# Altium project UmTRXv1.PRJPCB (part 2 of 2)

## Sheet EEpromConfig.SchDoc: BaseBand Front-End
size A3; Revision: 1; SheetNumber: 7
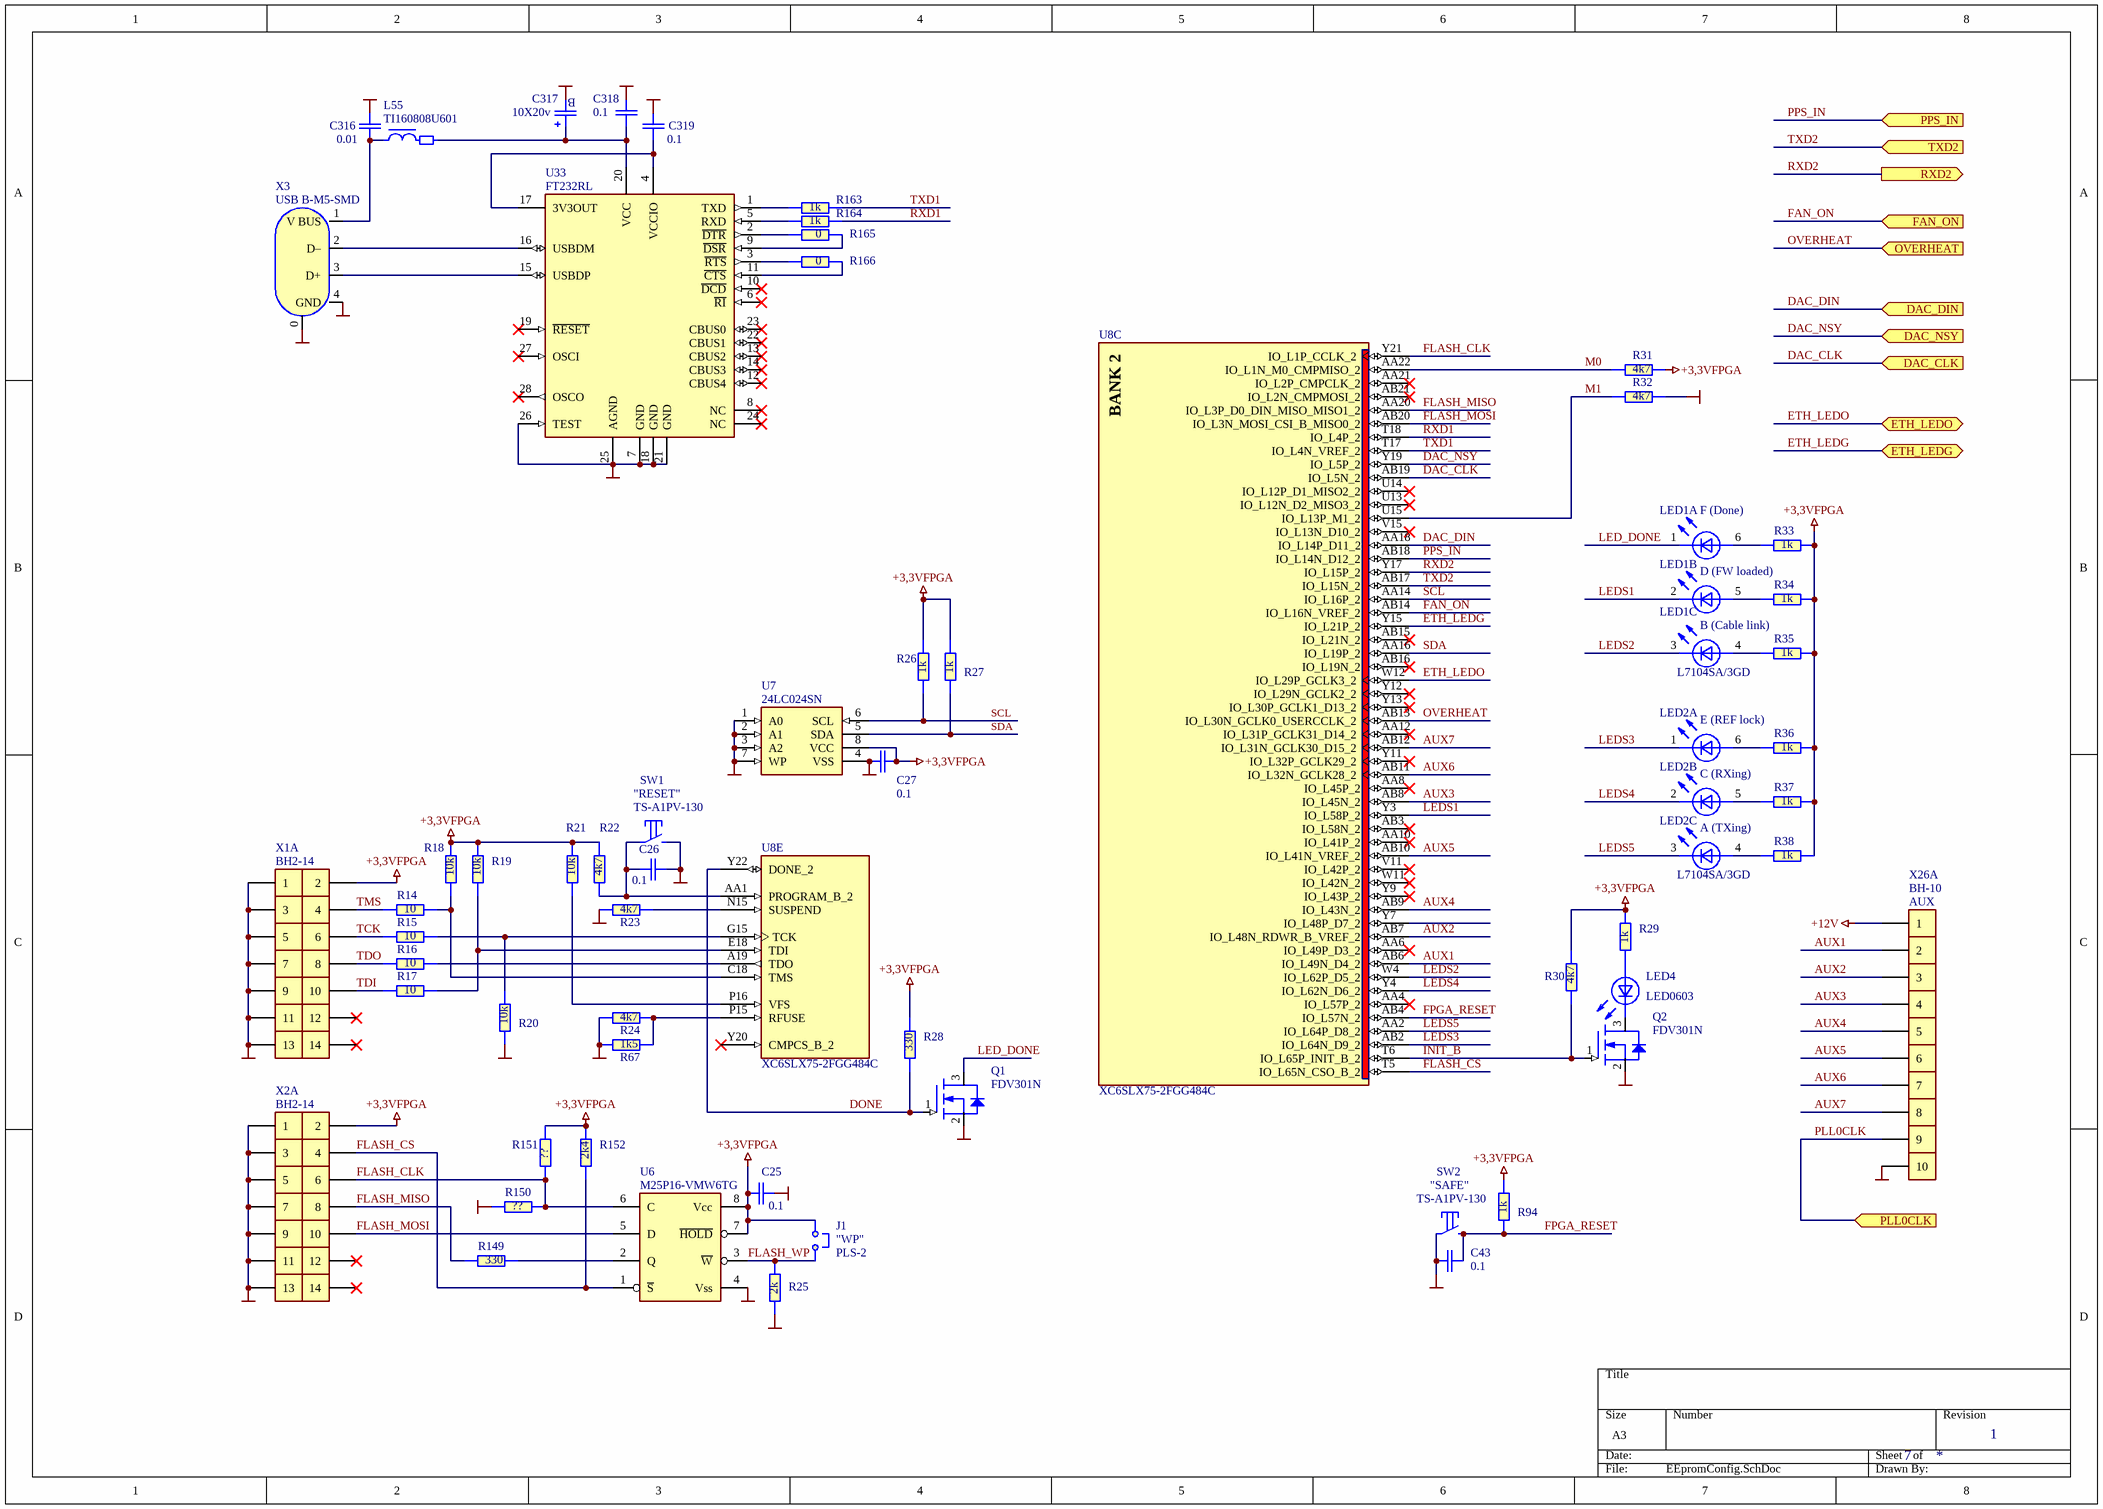
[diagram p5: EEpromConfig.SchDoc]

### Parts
C25  0.1  [C0402-Phillips]
C26  0.1  [C0402-Phillips]
C27  0.1  [C0402-Phillips]
C43  0.1  [C0402-Phillips]
C316  0.01  [C0603-PHILLIPS]
C317  10X20v  [CB3528]
C318  0.1  [C0603-PHILLIPS]
C319  0.1  [C0603-PHILLIPS]
J1  PLS-2  misc: "WP"  [PLT-2]
L55  TI160808U601  [Ti160808-Phillips]
LED1  L7104SA/3GD  [L-7104SA/3]  (value not drawn)  (parts A,B,C of 3)
LED2  L7104SA/3GD  [L-7104SA/3]  (value not drawn)  (parts A,B,C of 3)
LED4  LED0603  [LED-0603y]
Q1  FDV301N  [SOT23-Philips]
Q2  FDV301N  [SOT23-Philips]
R14  10  [R0603-PHILLIPS]
R15  10  [R0603-PHILLIPS]
R16  10  [R0603-PHILLIPS]
R17  10  [R0603-PHILLIPS]
R18  10k  [R0603-PHILLIPS]
R19  10k  [R0603-PHILLIPS]
R20  10k  [R0603-PHILLIPS]
R21  10k  [R0603-PHILLIPS]
R22  4k7  [R0603-PHILLIPS]
R23  4k7  [R0603-PHILLIPS]
R24  4k7  [R0603-PHILLIPS]
R25  2k  [R0603-PHILLIPS]
R26  1k  [R0603-PHILLIPS]
R27  1k  [R0603-PHILLIPS]
R28  330  [R0603-PHILLIPS]
R29  1k  [R0603-PHILLIPS]
R30  4k7  [R0603-PHILLIPS]
R31  4k7  [R0603-PHILLIPS]
R32  4k7  [R0603-PHILLIPS]
R33  1k  [R0603-PHILLIPS]
R34  1k  [R0603-PHILLIPS]
R35  1k  [R0603-PHILLIPS]
R36  1k  [R0603-PHILLIPS]
R37  1k  [R0603-PHILLIPS]
R38  1k  [R0603-PHILLIPS]
R67  1k5  [R0603-PHILLIPS]
R94  1k  [R0603-PHILLIPS]
R149  330  [R0603-PHILLIPS]
R150  ??  [R0603-PHILLIPS]
R151  ??  [R0603-PHILLIPS]
R152  2k4  [R0603-PHILLIPS]
R163  1k  [R0603-PHILLIPS]
R164  1k  [R0603-PHILLIPS]
R165  0  [R0603-PHILLIPS]
R166  0  [R0603-PHILLIPS]
SW1  TS-A1PV-130  misc: "RESET"  [KNOPKA]
SW2  TS-A1PV-130  misc: "SAFE"  [KNOPKA]
U6  M25P16-VMW6TG  [SOIC8]
U7  24LC024SN  [SOIC8]
U8  XC6SLX75-2FGG484C  [FBGA484]  (parts C,E of 8)
U33  FT232RL  [SSOP-28(5.3X10/0.65)]
X1  BH2-14  [BH2-14]  (value not drawn)  (parts A,B,C,D,E,F,G,H,I,J,K,L,M,N of 14)
X2  BH2-14  [BH2-14]  (value not drawn)  (parts A,B,C,D,E,F,G,H,I,J,K,L,M,N of 14)
X3  USB B-M5-SMD  [USB/SM0.8-6H5]
X26  BH-10  value AUX  [BH-10]  (parts A,B,C,D,E,F,G,H,I,J of 10)

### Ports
DAC_CLK (in), DAC_DIN (in), DAC_NSY (in), ETH_LEDG, ETH_LEDO, FAN_ON (in), OVERHEAT (in), PLL0CLK (in), PPS_IN (in), RXD2 (out), TXD2 (in)

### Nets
+3,3VFPGA: C25.1 C27.2 J1.1 R18.1 R19.1 R21.1 R22.1 R26.1 R27.1 R28.1 R29.1 R30.1 R31.2 R33.1 R34.1 R35.1 R36.1 R37.1 R38.1 R94.1 R151.1 R152.1 U6.7(~{HOLD}) U6.8(Vcc) U7.8(VCC) X1.2 X2.2
+12V: X26.1
GND: C25.2 C26.2 C27.1 C43.1 C316.1 C317.2(-) C318.1 C319.1 Q1.2(S) Q2.2(S) R20.2 R23.1 R24.1 R25.2 R32.2 R67.1 R150.1 SW1.2 SW2.1 U6.4(Vss) U7.1(A0) U7.2(A1) U7.3(A2) U7.4(VSS) U7.7(WP) U33.7(GND) U33.18(GND) U33.21(GND) U33.25(AGND) U33.26(TEST) X1.1 X1.3 X1.5 X1.7 X1.9 X1.11 X1.13 X2.1 X2.3 X2.5 X2.7 X2.9 X2.11 X2.13 X3.0(GND) X3.4(GND) X26.10
AUX1: U8.AB6(IO_L49N_D4_2) X26.2
AUX2: U8.AB7(IO_L48N_RDWR_B_VREF_2) X26.3
AUX3: U8.AB8(IO_L45N_2) X26.4
AUX4: U8.AB9(IO_L43N_2) X26.5
AUX5: U8.AB10(IO_L41N_VREF_2) X26.6
AUX6: U8.AB11(IO_L32N_GCLK28_2) X26.7
AUX7: U8.AB12(IO_L31N_GCLK30_D15_2) X26.8
DAC_CLK: U8.AB19(IO_L5N_2) ; port DAC_CLK
DAC_DIN: U8.AA18(IO_L14P_D11_2) ; port DAC_DIN
DAC_NSY: U8.Y19(IO_L5P_2) ; port DAC_NSY
DONE: Q1.1(G) R28.2 U8.Y22(DONE_2)
ETH_LEDG: U8.Y15(IO_L21P_2) ; port ETH_LEDG
ETH_LEDO: U8.W12(IO_L29P_GCLK3_2) ; port ETH_LEDO
FAN_ON: U8.AB14(IO_L16N_VREF_2) ; port FAN_ON
FLASH_CLK: R150.2 R151.2 U6.6(C) U8.Y21(IO_L1P_CCLK_2) X2.6
FLASH_CS: R152.2 U6.1(~{S}) U8.T5(IO_L65N_CSO_B_2) X2.4
FLASH_MISO: R149.1 U8.AA20(IO_L3P_D0_DIN_MISO_MISO1_2) X2.8
FLASH_MOSI: U6.5(D) U8.AB20(IO_L3N_MOSI_CSI_B_MISO0_2) X2.10
FLASH_WP: J1.2 R25.1 U6.3(~{W})
FPGA_RESET: C43.2 R94.2 SW2.2 U8.AB4(IO_L57N_2)
INIT_B: Q2.1(G) R30.2 U8.T6(IO_L65P_INIT_B_2)
LED_DONE: LED1.1(K1) Q1.3(D)
LEDS1: LED1.2(K2) U8.Y3(IO_L58P_2)
LEDS2: LED1.3(K3) U8.W4(IO_L62P_D5_2)
LEDS3: LED2.1(K1) U8.AB2(IO_L64N_D9_2)
LEDS4: LED2.2(K2) U8.Y4(IO_L62N_D6_2)
LEDS5: LED2.3(K3) U8.AA2(IO_L64P_D8_2)
M0: R31.1 U8.AA22(IO_L1N_M0_CMPMISO_2)
M1: R32.1 U8.U15(IO_L13P_M1_2)
OVERHEAT: U8.AB13(IO_L30N_GCLK0_USERCCLK_2) ; port OVERHEAT
PLL0CLK: X26.9 ; port PLL0CLK
PPS_IN: U8.AB18(IO_L14N_D12_2) ; port PPS_IN
RXD1: R164.1 U8.T18(IO_L4P_2)
RXD2: U8.Y17(IO_L15P_2) ; port RXD2
SCL: R26.2 U7.6(SCL) U8.AA14(IO_L16P_2)
SDA: R27.2 U7.5(SDA) U8.AA16(IO_L19P_2)
TCK: R15.1 X1.6
TDI: R17.1 X1.10
TDO: R16.1 X1.8
TMS: R14.1 X1.4
TXD1: R163.1 U8.T17(IO_L4N_VREF_2)
TXD2: U8.AB17(IO_L15N_2) ; port TXD2
NetC26_1: C26.1 R22.2 SW1.1 U8.AA1(PROGRAM_B_2)
NetC316_2: C316.2 L55.1 X3.1(V_BUS)
NetC317_1: C317.1(+) C318.2 L55.2 U33.20(VCC)
NetC319_2: C319.2 U33.4(VCCIO) U33.17(3V3OUT)
NetLED1_4: LED1.4(A3) R35.2
NetLED1_5: LED1.5(A2) R34.2
NetLED1_6: LED1.6(A1) R33.2
NetLED2_4: LED2.4(A3) R38.2
NetLED2_5: LED2.5(A2) R37.2
NetLED2_6: LED2.6(A1) R36.2
NetLED4_1: LED4.1(K) Q2.3(D)
NetLED4_2: LED4.2(A) R29.2
NetR14_2: R14.2 R18.2 U8.C18(TMS)
NetR15_2: R15.2 R20.1 U8.G15(TCK)
NetR16_2: R16.2 U8.A19(TDO)
NetR17_2: R17.2 R19.2 U8.E18(TDI)
NetR21_2: R21.2 U8.P16(VFS)
NetR23_2: R23.2 U8.N15(SUSPEND)
NetR24_2: R24.2 R67.2 U8.P15(RFUSE)
NetR149_2: R149.2 U6.2(Q)
NetR163_2: R163.2 U33.1(TXD)
NetR164_2: R164.2 U33.5(RXD)
NetR165_1: R165.1 U33.2(~{DTR})
NetR165_2: R165.2 U33.9(~{DSR})
NetR166_1: R166.1 U33.3(~{RTS})
NetR166_2: R166.2 U33.11(~{CTS})
NetU33_15: U33.15(USBDP) X3.3(D+)
NetU33_16: U33.16(USBDM) X3.2(D–)

Not connected (* = marked no-connect by the designer): U8 AA4(IO_L57P_2)* AA6(IO_L49P_D3_2)* AA8(IO_L45P_2)* AA10(IO_L41P_2)* AA12(IO_L31P_GCLK31_D14_2)* AA21(IO_L2P_CMPCLK_2)* AB3(IO_L58N_2)* AB15(IO_L21N_2)* AB16(IO_L19N_2)* AB21(IO_L2N_CMPMOSI_2)* U13(IO_L12N_D2_MISO3_2)* U14(IO_L12P_D1_MISO2_2)* V11(IO_L42P_2)* V15(IO_L13N_D10_2)* W11(IO_L42N_2)* Y7(IO_L48P_D7_2) Y9(IO_L43P_2)* Y11(IO_L32P_GCLK29_2)* Y12(IO_L29N_GCLK2_2)* Y13(IO_L30P_GCLK1_D13_2)* Y20(CMPCS_B_2)*; U33 6(~{RI})* 8(NC)* 10(~{DCD})* 12(CBUS4)* 13(CBUS2)* 14(CBUS3)* 19(~{RESET})* 22(CBUS1)* 23(CBUS0)* 24(NC)* 27(OSCI)* 28(OSCO)*; X1 12* 14*; X2 12* 14*

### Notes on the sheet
- F (Done)
- D (FW loaded)
- B (Cable link)
- E (REF lock)
- (near LED2) C (RXing)
- (near LED2) A (TXing)

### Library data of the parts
C25-C27 C43 = C0402: Конденсатор; Manufacturer: MURATA; Tolerance: 20%; Name: SMD0402; U/P/TKE: Y5V
C316 C318 C319 = C0603: Конденсатор; Manufacturer: MURATA; Tolerance: 20%; Name: SMD0603; U/P/TKE: Y5V
C317 = CB3528: Конденсатор; Manufacturer: SPRAGUE; Name: Case B; U/P/TKE: 20V
J1 = JUMP-2: Перемычка; Manufacturer: BM
L55 = TI160808: Дроссель ЭМС; Manufacturer: MURATA
LED1 LED2 = L7104SA/3: Светодиод; Manufacturer: KINGBRIGTH; PDF: d:\Proj\Components\Kingbright\L-7104SA-3GD(Ver.4).pdf
LED4 = LED0603: Светодиод
Q1 Q2 = FDV301N: Транзистор; Manufacturer: Fairchild; PDF: D:\Proj\Components\FairChild\FDV301N.pdf
R14-R38 R67 R94 R149-R152 R163-R166 = R0603: Резистор; Manufacturer: YAGEO; Tolerance: 5%; Name: SMD0603; U/P/TKE: 0.1W
SW1 SW2 = KNOPKA: Кнопка; Manufacturer: Alps
U6 = M25P40-VMN6T: Микросхема; Manufacturer: ST; Swap: No; PDF: d:\Proj\Components\ST\M25P40.pdf
U7 = AT24CXX: Микросхема; Manufacturer: Microchip; Swap: No; PDF: d:\Proj\components\Atmel\AT24C02A_04A_08A_16A.pdf; PDF2: d:\Proj\Components\Atmel\AT24C04B_08B.pdf
U8 = XC6SLX75-2FGG484C: Spartan-6 LX 1.2V FPGA, 270 User I/Os, 484-Ball Fine-Pitch BGA (1.0mm Pitch), Speed Grade 2, Commercial Grade, Pb-Free; Manufacturer: Xilinx
U33 = FT232RL: Микросхема; Manufacturer: FTDI; Misc: USB UART Asynchronous Serial Data Transfer Chip,
X1 X2 = BH2-14: Разъем; Manufacturer: BM
X3 = USB M-1J: Разъём
X26 = BH-10: Разъем; Manufacturer: BM

## Sheet Clocking.SchDoc: BaseBand Front-End
size A3; Revision: 1; SheetNumber: 5
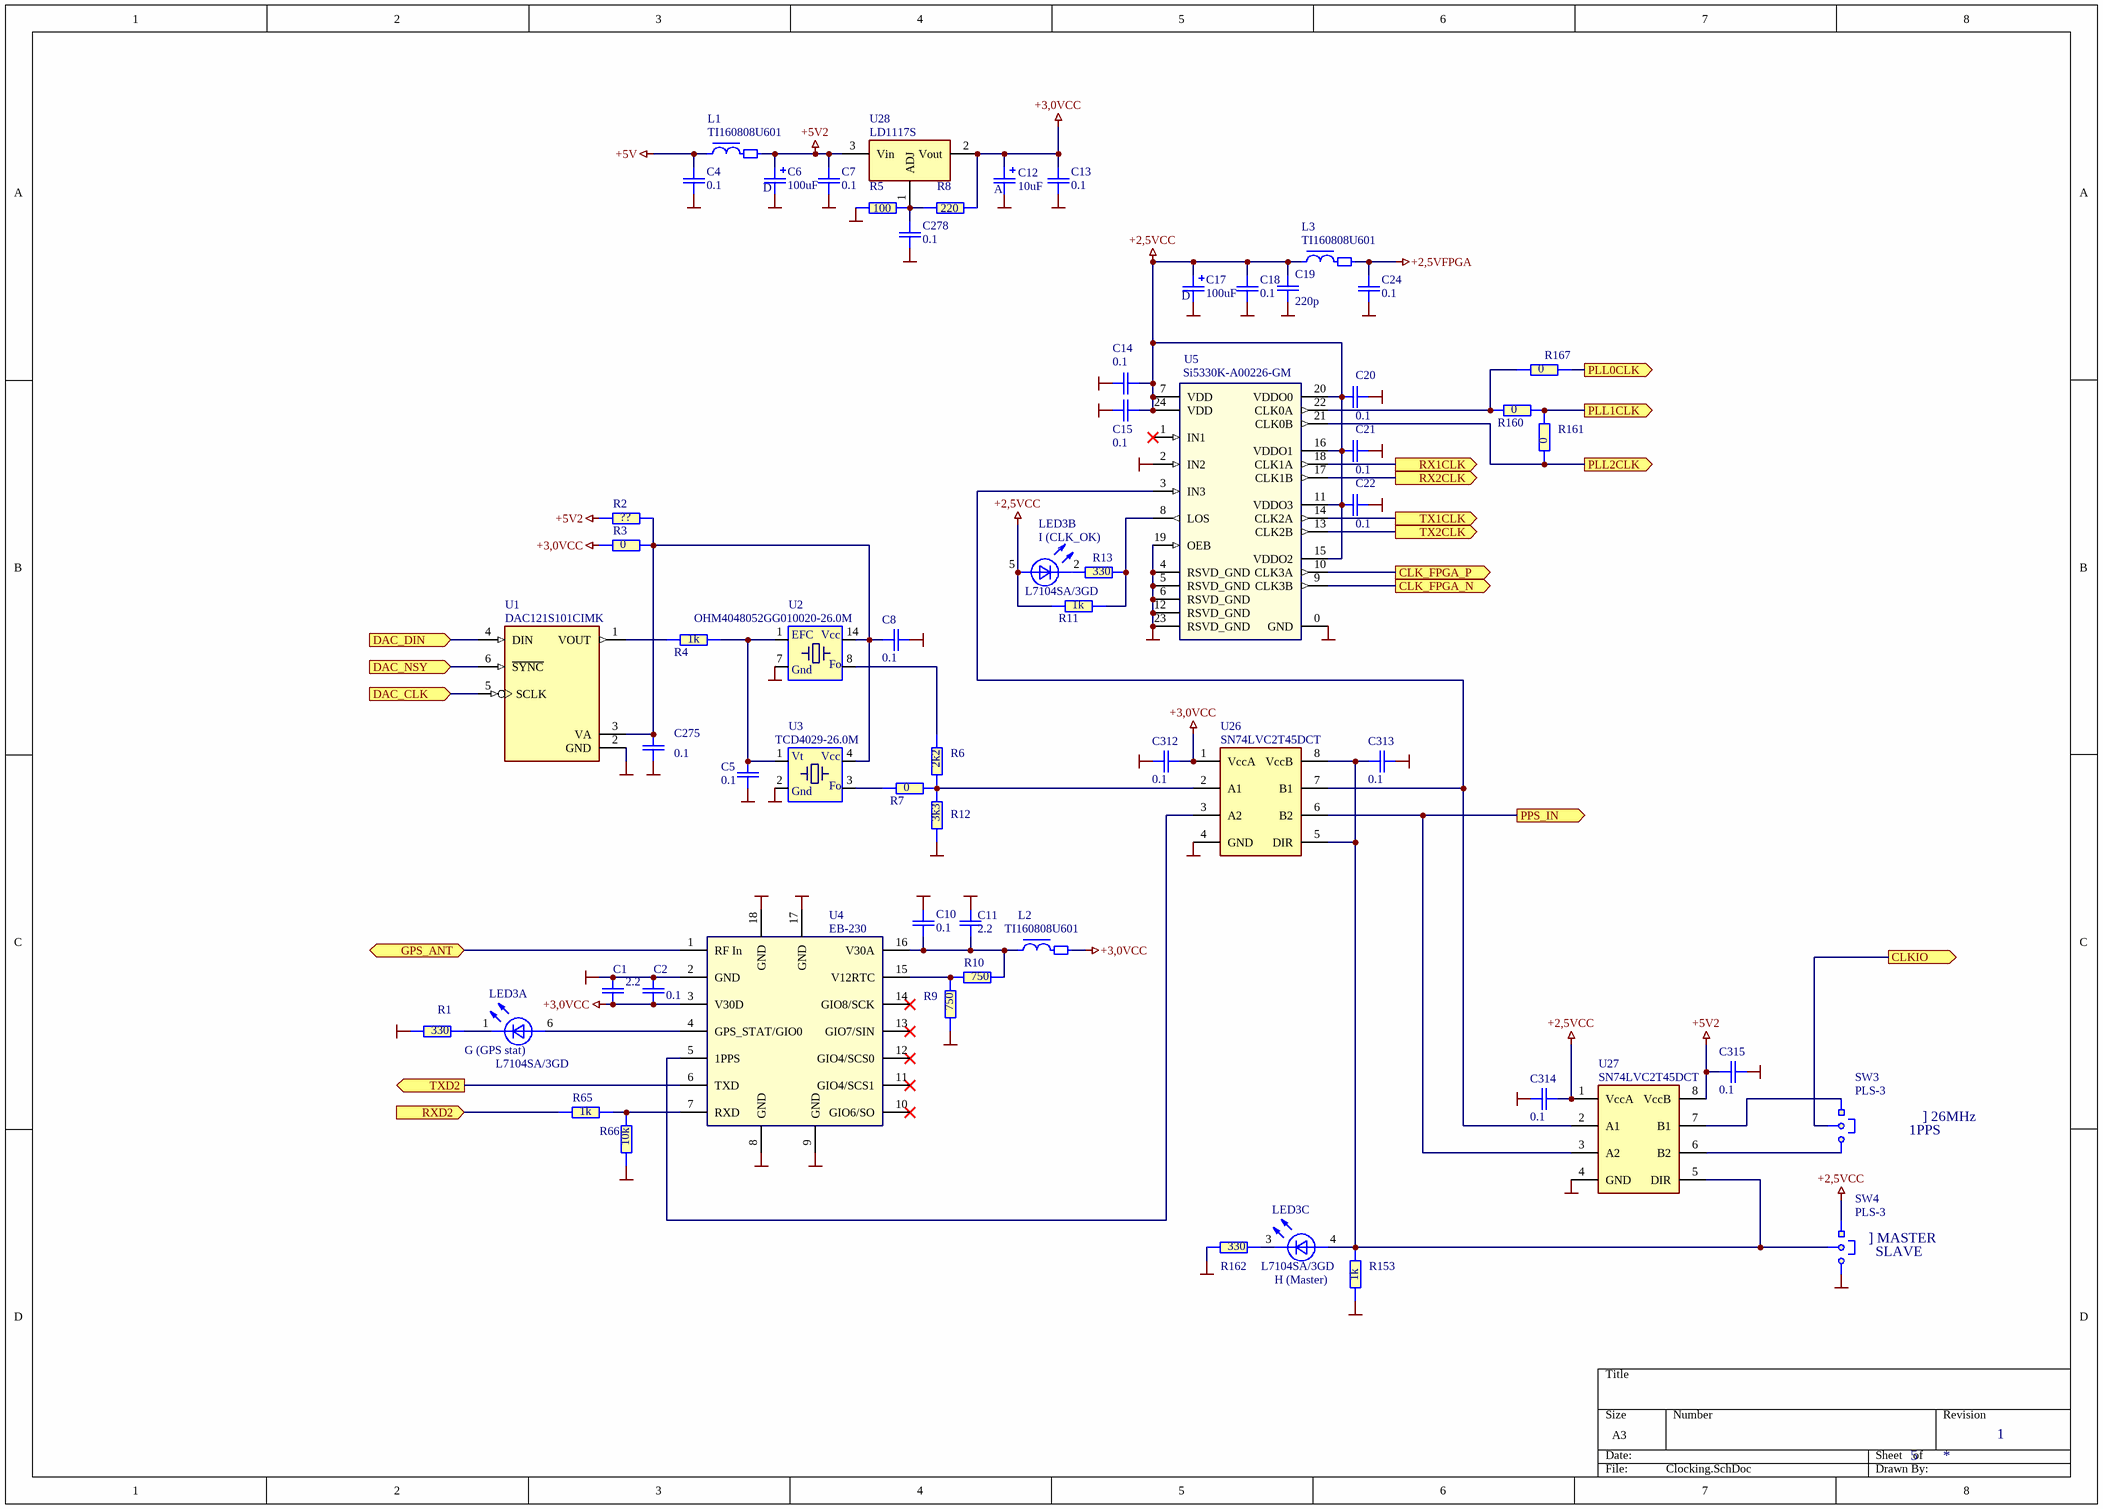
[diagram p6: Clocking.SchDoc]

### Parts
C1  2.2  [C0402-Phillips]
C2  0.1  [C0402-Phillips]
C4  0.1  [C0402-Phillips]
C5  0.1  [C0402-Phillips]
C6  100uF  [cd7343]
C7  0.1  [C0402-Phillips]
C8  0.1  [C0402-Phillips]
C10  0.1  [C0402-Phillips]
C11  2.2  [C0402-Phillips]
C12  10uF  [CA3216]
C13  0.1  [C0402-Phillips]
C14  0.1  [C0402-Phillips]
C15  0.1  [C0402-Phillips]
C17  100uF  [cd7343]
C18  0.1  [C0402-Phillips]
C19  220p  [C0603-PHILLIPS]
C20  0.1  [C0402-Phillips]
C21  0.1  [C0402-Phillips]
C22  0.1  [C0402-Phillips]
C24  0.1  [C0402-Phillips]
C275  0.1  [C0402-Phillips]
C278  0.1  [C0402-Phillips]
C312  0.1  [C0402-Phillips]
C313  0.1  [C0402-Phillips]
C314  0.1  [C0402-Phillips]
C315  0.1  [C0402-Phillips]
L1  TI160808U601  [Ti160808-Phillips]
L2  TI160808U601  [Ti160808-Phillips]
L3  TI160808U601  [Ti160808-Phillips]
LED3  L7104SA/3GD  [L-7104SA/3]  (parts A,B,C of 3)
R1  330  [R0603-PHILLIPS]
R2  ??  [R0603-PHILLIPS]
R3  0  [R0603-PHILLIPS]
R4  1k  [R0603-PHILLIPS]
R5  100  [R0603-PHILLIPS]
R6  2k2  [R0603-PHILLIPS]
R7  0  [R0603-PHILLIPS]
R8  220  [R0603-PHILLIPS]
R9  750  [R0603-PHILLIPS]
R10  750  [R0603-PHILLIPS]
R11  1k  [R0603-PHILLIPS]
R12  3k3  [R0603-PHILLIPS]
R13  330  [R0603-PHILLIPS]
R65  1k  [R0603-PHILLIPS]
R66  10k  [R0603-PHILLIPS]
R153  1k  [R0603-PHILLIPS]
R160  0  [R0603-PHILLIPS]
R161  0  [R0603-PHILLIPS]
R162  330  [R0603-PHILLIPS]
R167  0  [R0603-PHILLIPS]
SW3  PLS-3  [PLT-3]
SW4  PLS-3  [PLT-3]
U1  DAC121S101CIMK  [SOT-23-6]
U2  OHM4048052GG010020-26.0M  [DIL14-20x13,2]
U3  TCD4029-26.0M  [TCXO7X5]
U4  EB-230  [EB-230]
U5  Si5330K-A00226-GM  [QFN-24(4x4/0/5mm) with Pad]
U26  SN74LVC2T45DCT  [SO-8-MICRO]
U27  SN74LVC2T45DCT  [SO-8-MICRO]
U28  LD1117S  [SOT-223-1]

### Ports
CLK_FPGA_N (out), CLK_FPGA_P (out), CLKIO (out), DAC_CLK (in), DAC_DIN (in), DAC_NSY (in), GPS_ANT, PLL0CLK (out), PLL1CLK (out), PLL2CLK (out), PPS_IN (out), RX1CLK (out), RX2CLK (out), RXD2 (in), TX1CLK (out), TX2CLK (out), TXD2 (out)

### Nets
+2,5VCC: C14.2 C15.2 C17.1(+) C18.1 C19.1 C20.1 C21.1 C22.1 C314.1 L3.1 LED3.5(A2) R11.1 SW4.1 U5.7(VDD) U5.11(VDDO3) U5.15(VDDO2) U5.16(VDDO1) U5.20(VDDO0) U5.24(VDD) U27.1(VccA)
+2,5VFPGA: C24.1 L3.2
+3,0VCC: C1.1 C2.1 C12.1(+) C13.1 C312.1 L2.2 R3.1 R8.2 U4.3(V30D) U26.1(VccA) U28.2(Vout)
+5V: C4.1 L1.1
+5V2: C6.1(+) C7.1 C315.2 L1.2 R2.1 U27.8(VccB) U28.3(Vin)
GND: C1.2 C2.2 C4.2 C5.1 C6.2(-) C7.2 C8.2 C10.2 C11.2 C12.2(-) C13.2 C14.1 C15.1 C17.2(-) C18.2 C19.2 C20.2 C21.2 C22.2 C24.2 C275.1 C278.2 C312.2 C313.1 C314.2 C315.1 R1.1 R5.1 R9.1 R12.1 R66.1 R153.1 R162.1 SW4.3 U1.2(GND) U2.7(GND) U3.2(GND) U4.2(GND) U4.8(GND) U4.9(GND) U4.17(GND) U4.18(GND) U5.0(GND) U5.2(IN2) U5.4(RSVD_GND) U5.5(RSVD_GND) U5.6(RSVD_GND) U5.12(RSVD_GND) U5.19(OEB) U5.23(RSVD_GND) U26.4(GND) U27.4(GND)
CLK_FPGA_N: U5.9(CLK3B) ; port CLK_FPGA_N
CLK_FPGA_P: U5.10(CLK3A) ; port CLK_FPGA_P
CLKIO: SW3.2 ; port CLKIO
DAC_CLK: U1.5(SCLK) ; port DAC_CLK
DAC_DIN: U1.4(DIN) ; port DAC_DIN
DAC_NSY: U1.6(~{SYNC}) ; port DAC_NSY
GPS_ANT: U4.1(RF_In) ; port GPS_ANT
PLL0CLK: R167.2 ; port PLL0CLK
PLL1CLK: R160.2 R161.1 ; port PLL1CLK
PLL2CLK: R161.2 U5.21(CLK0B) ; port PLL2CLK
PPS_IN: U26.6(B2) U27.3(A2) ; port PPS_IN
RX1CLK: U5.18(CLK1A) ; port RX1CLK
RX2CLK: U5.17(CLK1B) ; port RX2CLK
RXD2: R65.1 ; port RXD2
TX1CLK: U5.14(CLK2A) ; port TX1CLK
TX2CLK: U5.13(CLK2B) ; port TX2CLK
TXD2: U4.6(TXD) ; port TXD2
NetC5_2: C5.2 R4.2 U2.1(EFC) U3.1(Vtune)
NetC8_1: C8.1 C275.2 R2.2 R3.2 U1.3(VA) U2.14(VCC) U3.4(VCC)
NetC10_1: C10.1 C11.1 L2.1 R10.2 U4.16(V30A)
NetC278_1: C278.1 R5.2 R8.1 U28.1(ADJ)
NetC313_2: C313.2 LED3.4(A3) R153.2 SW4.2 U26.5(DIR) U26.8(VccB) U27.5(DIR)
NetLED3_1: LED3.1(K1) R1.2
NetLED3_2: LED3.2(K2) R13.1
NetLED3_3: LED3.3(K3) R162.2
NetLED3_6: LED3.6(A1) U4.4(GPS_STAT/GIO0)
NetR4_1: R4.1 U1.1(VOUT)
NetR6_1: R6.1 U2.8(Fo)
NetR6_2: R6.2 R7.2 R12.2 U26.2(A1)
NetR7_1: R7.1 U3.3(Fo)
NetR9_2: R9.2 R10.1 U4.15(V12RTC)
NetR11_2: R11.2 R13.2 U5.8(LOS)
NetR65_2: R65.2 R66.2 U4.7(RXD)
NetR160_1: R160.1 R167.1 U5.22(CLK0A)
NetSW3_1: SW3.1 U27.7(B1)
NetSW3_3: SW3.3 U27.6(B2)
NetU4_5: U4.5(1PPS) U26.3(A2)
NetU5_3: U5.3(IN3) U26.7(B1) U27.2(A1)

Not connected (* = marked no-connect by the designer): U4 10(GIO6/SO)* 11(GIO4/SCS1)* 12(GIO4/SCS0)* 13(GIO7/SIN)* 14(GIO8/SCK)*; U5 1(IN1)*

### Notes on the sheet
- I (CLK_OK)
- G (GPS stat)
- (near SW3) ] 26MHz
- (near SW3) 1PPS
- (near SW4) ] MASTER
- (near SW4) SLAVE
- H (Master)

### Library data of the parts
C1 C2 C4 C5 C7 C8 C10 C11 C13-C15 C18 C20-C22 C24 C275 C278 C312-C315 = C0402: as C25-C27 on sheet EEpromConfig
C6 C17 = CD7343: Конденсатор; Manufacturer: SPRAGUE; Name: CASE-G; U/P/TKE: 16V
C12 = CA3216: Конденсатор; Manufacturer: SPRAGUE; Name: Case A; U/P/TKE: 10V
C19 = C0603: Конденсатор; Manufacturer: MURATA; Tolerance: 20%; Name: SMD0603; U/P/TKE: NP0
L1-L3 = TI160808: Дроссель ЭМС; Manufacturer: MURATA
LED3 = L7104SA/3: as LED1 on sheet EEpromConfig
R1-R13 R65 R66 R153 R160-R162 R167 = R0603: as R14-R38 on sheet EEpromConfig
SW3 SW4 = JUMP-3: Перемычка; Manufacturer: BM
U1 = DAC121S101CIMK: Микросхема; Manufacturer: National Semiconductor; Misc: 12-Bit Micro Power Digital-to-Analog Converter with Rail-to-Rail Output
U2 = OCVCXO: Manufacturer: Pletronics; Misc: TCXO
U3 = TCVCXO_5X3: TCVCXO; Manufacturer: Jauch; Misc: TCXO
U4 = EB-230: Модуль; Manufacturer: Transistem; PDF: d:\Proj\Components\OnSemiconductors\SMFxxC.pdf; Misc: GPS engine board
U5 = SI5330: Микросхема; Manufacturer: Silicon Laboratoryes; Misc: CLOCK BUFFER/LEVEL TRANSLATOR; Swap: No
U26 U27 = 74LVC2T45DCT: Микросхема; Manufacturer: TI; Swap: No
U28 = LD1117ADJ: Микросхема; Manufacturer: STMicro; Swap: No

## Sheet LMS.SchDoc
size A3; Revision: 1; SheetNumber: 3
Used 2 times, as channels LMS-a, LMS-b. Parts and nets are listed once, with the designators drawn on the sheet.
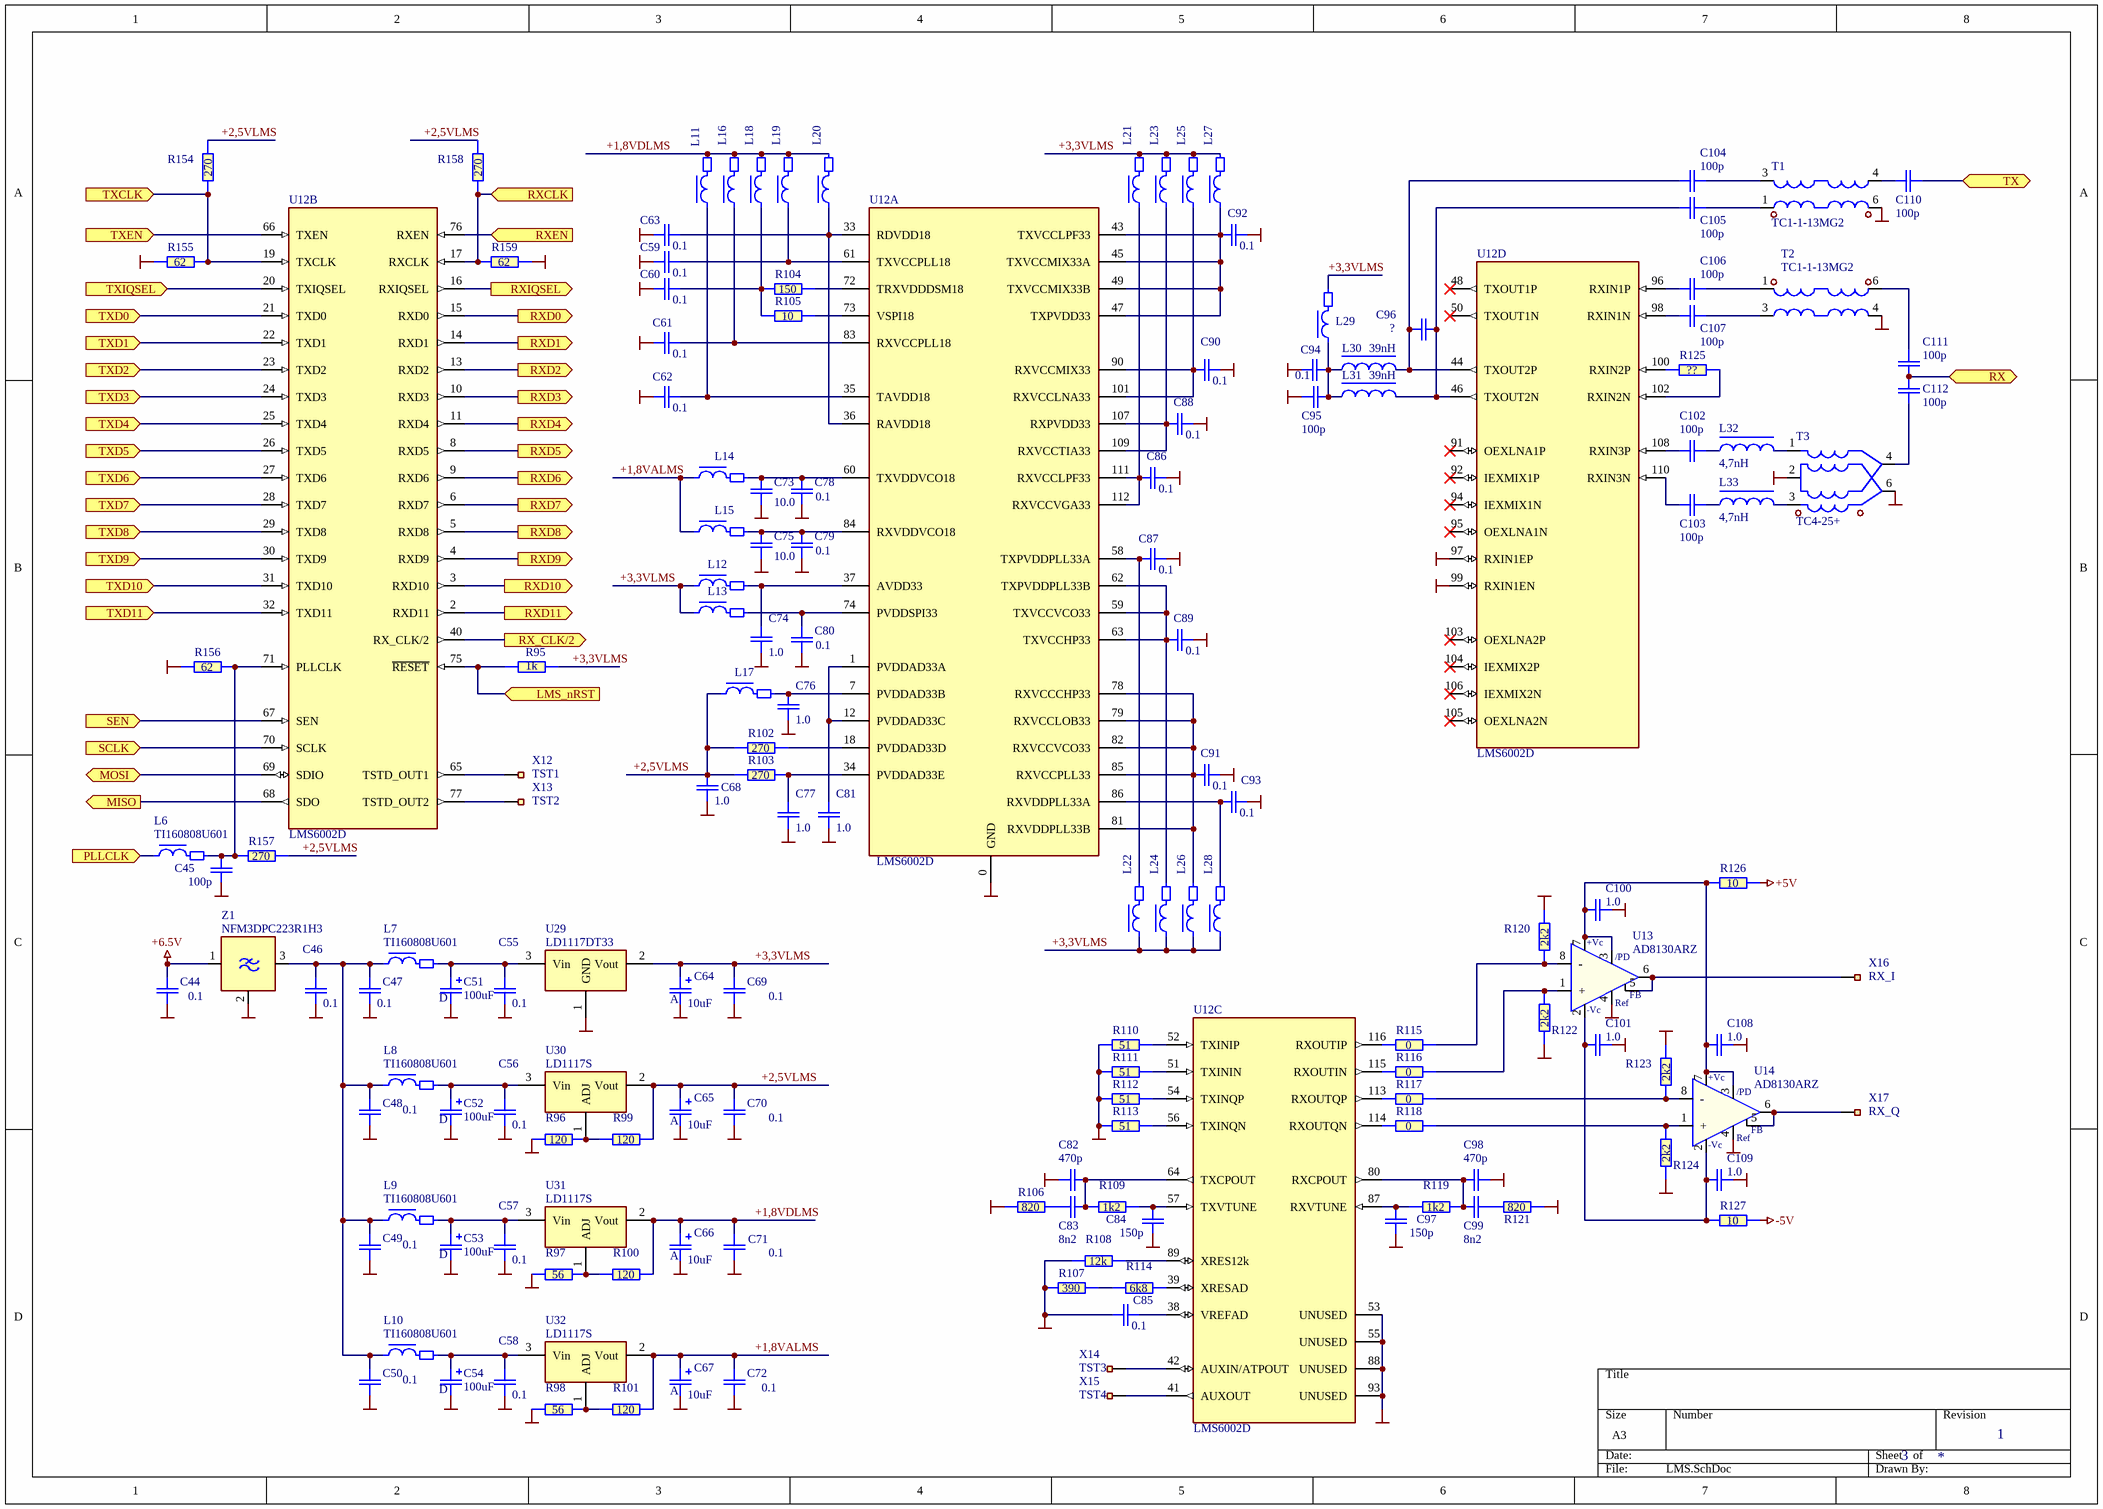
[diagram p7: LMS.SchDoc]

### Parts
C44  0.1  [C0402-Phillips]
C45  100p  [C0603-PHILLIPS]
C46  0.1  [C0402-Phillips]
C47  0.1  [C0402-Phillips]
C48  0.1  [C0402-Phillips]
C49  0.1  [C0402-Phillips]
C50  0.1  [C0402-Phillips]
C51  100uF  [cd7343]
C52  100uF  [cd7343]
C53  100uF  [cd7343]
C54  100uF  [cd7343]
C55  0.1  [C0402-Phillips]
C56  0.1  [C0402-Phillips]
C57  0.1  [C0402-Phillips]
C58  0.1  [C0402-Phillips]
C59  0.1  [C0402-Phillips]
C60  0.1  [C0402-Phillips]
C61  0.1  [C0402-Phillips]
C62  0.1  [C0402-Phillips]
C63  0.1  [C0402-Phillips]
C64  10uF  [CA3216]
C65  10uF  [CA3216]
C66  10uF  [CA3216]
C67  10uF  [CA3216]
C68  1.0  [C0603-PHILLIPS]
C69  0.1  [C0402-Phillips]
C70  0.1  [C0402-Phillips]
C71  0.1  [C0402-Phillips]
C72  0.1  [C0402-Phillips]
C73  10.0  [C0603-Phillips]
C74  1.0  [C0603-PHILLIPS]
C75  10.0  [C0603-Phillips]
C76  1.0  [C0603-PHILLIPS]
C77  1.0  [C0603-PHILLIPS]
C78  0.1  [C0402-Phillips]
C79  0.1  [C0402-cirq]
C80  0.1  [C0402-cirq]
C81  1.0  [C0603-PHILLIPS]
C82  470p  [C0603-PHILLIPS]
C83  8n2  [C0603-PHILLIPS]
C84  150p  [C0603-PHILLIPS]
C85  0.1  [C0402-Phillips]
C86  0.1  [C0402-Phillips]
C87  0.1  [C0402-Phillips]
C88  0.1  [C0402-cirq]
C89  0.1  [C0402-cirq]
C90  0.1  [C0402-Phillips]
C91  0.1  [C0402-Phillips]
C92  0.1  [C0402-cirq]
C93  0.1  [C0402-Phillips]
C94  0.1  [C0402-Phillips]
C95  100p  [C0603-PHILLIPS]
C96  ?  [C0603-PHILLIPS]
C97  150p  [C0603-PHILLIPS]
C98  470p  [C0603-PHILLIPS]
C99  8n2  [C0603-PHILLIPS]
C100  1.0  [C0603-PHILLIPS]
C101  1.0  [C0603-PHILLIPS]
C102  100p  [C0603-PHILLIPS]
C103  100p  [C0603-PHILLIPS]
C104  100p  [C0603-PHILLIPS]
C105  100p  [C0603-PHILLIPS]
C106  100p  [C0603-PHILLIPS]
C107  100p  [C0603-PHILLIPS]
C108  1.0  [C0603-PHILLIPS]
C109  1.0  [C0603-PHILLIPS]
C110  100p  [C0603-PHILLIPS]
C111  100p  [C0603-PHILLIPS]
C112  100p  [C0603-PHILLIPS]
L6  TI160808U601  [Ti160808-Phillips]
L7  TI160808U601  [Ti160808-Phillips]
L8  TI160808U601  [Ti160808-Phillips]
L9  TI160808U601  [Ti160808-Phillips]
L10  TI160808U601  [Ti160808-Phillips]
L11  TI160808U601  [Ti160808-Phillips]  (value not drawn)
L12  TI160808U601  [Ti160808-Phillips]  (value not drawn)
L13  TI160808U601  [Ti160808-Phillips]  (value not drawn)
L14  TI160808U601  [Ti160808-Phillips]  (value not drawn)
L15  TI160808U601  [Ti160808-Phillips]  (value not drawn)
L16  TI160808U601  [Ti160808-Phillips]  (value not drawn)
L17  TI160808U601  [Ti160808-Phillips]  (value not drawn)
L18  TI160808U601  [Ti160808-Phillips]  (value not drawn)
L19  TI160808U601  [Ti160808-Phillips]  (value not drawn)
L20  TI160808U601  [Ti160808-Phillips]  (value not drawn)
L21  TI160808U601  [Ti160808-Phillips]  (value not drawn)
L22  TI160808U601  [Ti160808-Phillips]  (value not drawn)
L23  TI160808U601  [Ti160808-Phillips]  (value not drawn)
L24  TI160808U601  [Ti160808-Phillips]  (value not drawn)
L25  TI160808U601  [Ti160808-Phillips]  (value not drawn)
L26  TI160808U601  [Ti160808-Phillips]  (value not drawn)
L27  TI160808U601  [Ti160808-Phillips]  (value not drawn)
L28  TI160808U601  [Ti160808-Phillips]  (value not drawn)
L29  TI160808U601  [Ti160808-Phillips]  (value not drawn)
L30  39nH  [TF160808-Phillips]
L31  39nH  [TF160808-Phillips]
L32  4,7nH  [TF160808-Phillips]
L33  4,7nH  [TF160808-Phillips]
R95  1k  [R0603-PHILLIPS]
R96  120  [R0603-PHILLIPS]
R97  56  [R0603-PHILLIPS]
R98  56  [R0603-PHILLIPS]
R99  120  [R0603-PHILLIPS]
R100  120  [R0603-PHILLIPS]
R101  120  [R0603-PHILLIPS]
R102  270  [R0603-PHILLIPS]
R103  270  [R0603-PHILLIPS]
R104  150  [R0603-PHILLIPS]
R105  10  [R0603-PHILLIPS]
R106  820  [R0603-PHILLIPS]
R107  390  [R0603-PHILLIPS]
R108  12k  [R0603-PHILLIPS]
R109  1k2  [R0603-PHILLIPS]
R110  51  [R0603-PHILLIPS]
R111  51  [R0603-PHILLIPS]
R112  51  [R0603-PHILLIPS]
R113  51  [R0603-PHILLIPS]
R114  6k8  [R0603-PHILLIPS]
R115  0  [R0603-PHILLIPS]
R116  0  [R0603-PHILLIPS]
R117  0  [R0603-PHILLIPS]
R118  0  [R0603-PHILLIPS]
R119  1k2  [R0603-PHILLIPS]
R120  2k2  [R0603-PHILLIPS]
R121  820  [R0603-PHILLIPS]
R122  2k2  [R0603-PHILLIPS]
R123  2k2  [R0603-PHILLIPS]
R124  2k2  [R0603-PHILLIPS]
R125  ??  [R0603-PHILLIPS]
R126  10  [R0603-PHILLIPS]
R127  10  [R0603-PHILLIPS]
R154  270  [R0603-PHILLIPS]
R155  62  [R0603-PHILLIPS]
R156  62  [R0603-PHILLIPS]
R157  270  [R0603-PHILLIPS]
R158  270  [R0603-PHILLIPS]
R159  62  [R0603-PHILLIPS]
T1  TC1-1-13MG2  [AT224-1]
T2  TC1-1-13MG2  [AT224-1]
T3  TC4-25+  [AT224-1]
U12  LMS6002D  [DQFN120(9x9/0.5mm)]  (parts A,B,C,D of 4)
U13  AD8130ARZ  [SO-8]
U14  AD8130ARZ  [SO-8]
U29  LD1117DT33  [to-252]
U30  LD1117S  [SOT-223-1]
U31  LD1117S  [SOT-223-1]
U32  LD1117S  [SOT-223-1]
X12  TST1  [kp40x40]
X13  TST2  [kp40x40]
X14  TST3  [kp40x40]
X15  TST4  [kp40x40]
X16  RX_I  [kp40x40]
X17  RX_Q  [kp40x40]
Z1  NFM3DPC223R1H3  [NFM3DP]

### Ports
LMS_nRST (in), MISO (out), MOSI (bidir), PLLCLK (in), RX, RX_CLK/2 (out), RXCLK (in), RXD0 (out), RXD1 (out), RXD2 (out), RXD3 (out), RXD4 (out), RXD5 (out), RXD6 (out), RXD7 (out), RXD8 (out), RXD9 (out), RXD10 (out), RXD11 (out), RXEN (in), RXIQSEL (out), SCLK (in), SEN (in), TX, TXCLK (in), TXD0 (in), TXD1 (in), TXD2 (in), TXD3 (in), TXD4 (in), TXD5 (in), TXD6 (in), TXD7 (in), TXD8 (in), TXD9 (in), TXD10 (in), TXD11 (in), TXEN (in), TXIQSEL (in)

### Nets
+5V: R126.2
+6.5V: C44.1 Z1.1
-5V: R127.2
GND: C44.2 C45.1 C46.2 C47.2 C48.2 C49.2 C50.2 C51.2(-) C52.2(-) C53.2(-) C54.2(-) C55.2 C56.2 C57.2 C58.2 C59.1 C60.1 C61.1 C62.1 C63.1 C64.2(-) C65.2(-) C66.2(-) C67.2(-) C68.2 C69.2 C70.2 C71.2 C72.2 C73.2 C74.2 C75.2 C76.2 C77.2 C78.2 C79.2 C80.2 C81.2 C82.2 C84.1 C85.1 C86.2 C87.2 C88.2 C89.2 C90.2 C91.2 C92.2 C93.2 C94.1 C95.2 C97.1 C98.2 C100.2 C101.2 C108.2 C109.2 R96.1 R97.1 R98.1 R106.1 R107.1 R108.1 R110.1 R111.1 R112.1 R113.1 R120.1 R121.2 R122.2 R123.1 R124.2 R155.1 R156.1 R159.2 T1.6(Pri_Dot) T2.4(Pri) T3.2(Sec_CT) T3.6(Pri_Dot) U12.0(GND) U12.53(UNUSED) U12.55(UNUSED) U12.88(UNUSED) U12.93(UNUSED) U12.97(RXIN1EP) U12.99(RXIN1EN) U13.4(REF) U14.4(REF) U29.1(GND) Z1.2
+1,8VALMS: C67.1(+) C72.1 L14.1 L15.1 R101.2 U32.2(Vout)
+1,8VDLMS: C66.1(+) C71.1 L11.2 L16.2 L18.2 L19.2 L20.2 R100.2 U31.2(Vout)
+2,5VLMS: C65.1(+) C68.1 C70.1 L17.1 R99.2 R102.1 R103.1 R154.1 R157.2 R158.1 U30.2(Vout)
+3,3VLMS: C64.1(+) C69.1 L12.1 L13.1 L21.2 L22.1 L23.2 L24.1 L25.2 L26.1 L27.2 L28.1 L29.2 R95.2 U29.2(Vout)
LMS_nRST: R95.1 U12.75(~{RESET}) ; port LMS_nRST
MISO: U12.68(SDO) ; port MISO
MOSI: U12.69(SDIO) ; port MOSI
PLLCLK: L6.1 ; port PLLCLK
RX: C111.1 C112.2 ; port RX
RX_CLK/2: U12.40(RX_CLK/2) ; port RX_CLK/2
RXCLK: R158.2 R159.1 U12.17(RXCLK) ; port RXCLK
RXD0: U12.15(RXD0) ; port RXD0
RXD1: U12.14(RXD1) ; port RXD1
RXD2: U12.13(RXD2) ; port RXD2
RXD3: U12.10(RXD3) ; port RXD3
RXD4: U12.11(RXD4) ; port RXD4
RXD5: U12.8(RXD5) ; port RXD5
RXD6: U12.9(RXD6) ; port RXD6
RXD7: U12.6(RXD7) ; port RXD7
RXD8: U12.5(RXD8) ; port RXD8
RXD9: U12.4(RXD9) ; port RXD9
RXD10: U12.3(RXD10) ; port RXD10
RXD11: U12.2(RXD11) ; port RXD11
RXEN: U12.76(RXEN) ; port RXEN
RXIQSEL: U12.16(RXIQSEL) ; port RXIQSEL
SCLK: U12.70(SCLK) ; port SCLK
SEN: U12.67(SEN) ; port SEN
TX: C110.2 ; port TX
TXCLK: R154.2 R155.2 U12.19(TXCLK) ; port TXCLK
TXD0: U12.21(TXD0) ; port TXD0
TXD1: U12.22(TXD1) ; port TXD1
TXD2: U12.23(TXD2) ; port TXD2
TXD3: U12.24(TXD3) ; port TXD3
TXD4: U12.25(TXD4) ; port TXD4
TXD5: U12.26(TXD5) ; port TXD5
TXD6: U12.27(TXD6) ; port TXD6
TXD7: U12.28(TXD7) ; port TXD7
TXD8: U12.29(TXD8) ; port TXD8
TXD9: U12.30(TXD9) ; port TXD9
TXD10: U12.31(TXD10) ; port TXD10
TXD11: U12.32(TXD11) ; port TXD11
TXEN: U12.66(TXEN) ; port TXEN
TXIQSEL: U12.20(TXIQSEL) ; port TXIQSEL
NetC45_2: C45.2 L6.2 R156.2 R157.1 U12.71(PLLCLK)
NetC46_1: C46.1 C47.1 C48.1 C49.1 C50.1 L7.1 L8.1 L9.1 L10.1 Z1.3
NetC51_1: C51.1(+) C55.1 L7.2 U29.3(Vin)
NetC52_1: C52.1(+) C56.1 L8.2 U30.3(Vin)
NetC53_1: C53.1(+) C57.1 L9.2 U31.3(Vin)
NetC54_1: C54.1(+) C58.1 L10.2 U32.3(Vin)
NetC59_2: C59.2 L19.1 U12.61(TXVCCPLL18)
NetC60_2: C60.2 L18.1 R104.1 R105.1
NetC61_2: C61.2 L16.1 U12.83(RXVCCPLL18)
NetC62_2: C62.2 L11.1 U12.35(TAVDD18)
NetC63_2: C63.2 L20.1 U12.33(RDVDD18) U12.36(RAVDD18)
NetC73_1: C73.1 C78.1 L14.2 U12.60(TXVDDVCO18)
NetC74_1: C74.1 L12.2 U12.37(AVDD33)
NetC75_1: C75.1 C79.1 L15.2 U12.84(RXVDDVCO18)
NetC76_1: C76.1 L17.2 U12.7(PVDDAD33B)
NetC77_1: C77.1 R103.2 U12.34(PVDDAD33E)
NetC80_1: C80.1 L13.2 U12.74(PVDDSPI33)
NetC81_1: C81.1 U12.1(PVDDAD33A) U12.12(PVDDAD33C)
NetC82_1: C82.1 C83.1 R109.1 U12.64(TXCPOUT)
NetC83_2: C83.2 R106.2
NetC84_2: C84.2 R109.2 U12.57(TXVTUNE)
NetC85_2: C85.2 U12.38(VREFAD)
NetC86_1: C86.1 L21.1 U12.111(RXVCCLPF33) U12.112(RXVCCVGA33)
NetC87_1: C87.1 L22.2 U12.58(TXPVDDPLL33A)
NetC88_1: C88.1 L23.1 U12.107(RXPVDD33) U12.109(RXVCCTIA33)
NetC89_1: C89.1 L24.2 U12.59(TXVCCVCO33) U12.62(TXPVDDPLL33B) U12.63(TXVCCHP33)
NetC90_1: C90.1 L25.1 U12.90(RXVCCMIX33) U12.101(RXVCCLNA33)
NetC91_1: C91.1 L26.2 U12.78(RXVCCCHP33) U12.79(RXVCCLOB33) U12.81(RXVDDPLL33B) U12.82(RXVCCVCO33) U12.85(RXVCCPLL33)
NetC92_1: C92.1 L27.1 U12.43(TXVCCLPF33) U12.45(TXVCCMIX33A) U12.47(TXPVDD33) U12.49(TXVCCMIX33B)
NetC93_1: C93.1 L28.2 U12.86(RXVDDPLL33A)
NetC94_2: C94.2 C95.1 L29.1 L30.1 L31.1
NetC96_1: C96.1 C105.1 L31.2 U12.46(TXOUT2N)
NetC96_2: C96.2 C104.1 L30.2 U12.44(TXOUT2P)
NetC97_2: C97.2 R119.1 U12.87(RXVTUNE)
NetC98_1: C98.1 C99.1 R119.2 U12.80(RXCPOUT)
NetC99_2: C99.2 R121.1
NetC100_1: C100.1 C108.1 R126.1 U13.3(~{PD}) U13.7(+Vc) U14.3(~{PD}) U14.7(+Vc)
NetC101_1: C101.1 C109.1 R127.1 U13.2(Vc-) U14.2(Vc-)
NetC102_1: C102.1 U12.108(RXIN3P)
NetC102_2: C102.2 L32.1
NetC103_1: C103.1 U12.110(RXIN3N)
NetC103_2: C103.2 L33.1
NetC104_2: C104.2 T1.3(Sec_Dot)
NetC105_2: C105.2 T1.1(Sec)
NetC106_1: C106.1 U12.96(RXIN1P)
NetC106_2: C106.2 T2.1(Sec)
NetC107_1: C107.1 U12.98(RXIN1N)
NetC107_2: C107.2 T2.3(Sec_Dot)
NetC110_1: C110.1 T1.4(Pri)
NetC111_2: C111.2 T2.6(Pri_Dot)
NetC112_1: C112.1 T3.4(Pri)
NetL32_2: L32.2 T3.1(Sec)
NetL33_2: L33.2 T3.3(Sec_Dot)
NetR96_2: R96.2 R99.1 U30.1(ADJ)
NetR97_2: R97.2 R100.1 U31.1(ADJ)
NetR98_2: R98.2 R101.1 U32.1(ADJ)
NetR102_2: R102.2 U12.18(PVDDAD33D)
NetR104_2: R104.2 U12.72(TRXVDDDSM18)
NetR105_2: R105.2 U12.73(VSPI18)
NetR107_2: R107.2 R114.1
NetR108_2: R108.2 U12.89(XRES12k)
NetR110_2: R110.2 U12.52(TXINIP)
NetR111_2: R111.2 U12.51(TXININ)
NetR112_2: R112.2 U12.54(TXINQP)
NetR113_2: R113.2 U12.56(TXINQN)
NetR114_2: R114.2 U12.39(XRESAD)
NetR115_1: R115.1 U12.116(RXOUTIP)
NetR115_2: R115.2 R120.2 U13.8(-)
NetR116_1: R116.1 U12.115(RXOUTIN)
NetR116_2: R116.2 R122.1 U13.1(+)
NetR117_1: R117.1 U12.113(RXOUTQP)
NetR117_2: R117.2 R123.2 U14.8(-)
NetR118_1: R118.1 U12.114(RXOUTQN)
NetR118_2: R118.2 R124.1 U14.1(+)
NetR125_1: R125.1 U12.100(RXIN2P)
NetR125_2: R125.2 U12.102(RXIN2N)
NetU12_41: U12.41(AUXOUT) X15.1
NetU12_42: U12.42(AUXIN/ATPOUT) X14.1
NetU12_65: U12.65(TSTD_OUT1) X12.1
NetU12_77: U12.77(TSTD_OUT2) X13.1
NetU13_5: U13.5(FB) U13.6(Out) X16.1
NetU14_5: U14.5(FB) U14.6(Out) X17.1

Not connected (* = marked no-connect by the designer): U12 48(TXOUT1P)* 50(TXOUT1N)* 91(OEXLNA1P)* 92(IEXMIX1P)* 94(IEXMIX1N)* 95(OEXLNA1N)* 103(OEXLNA2P)* 104(IEXMIX2P)* 105(OEXLNA2N)* 106(IEXMIX2N)*

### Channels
LMS-a: designators end in -1; ports LMS_nRST=LMS1_nRST MISO=MISO1 MOSI=MOSI1 PLLCLK=PLL1CLK RX=RX RX_CLK/2=RX1_CLK/2 RXCLK=RX1CLK RXD0=RX1D0 RXD1=RX1D1 RXD2=RX1D2 RXD3=RX1D3 RXD4=RX1D4 RXD5=RX1D5 RXD6=RX1D6 RXD7=RX1D7 RXD8=RX1D8 RXD9=RX1D9 RXD10=RX1D10 RXD11=RX1D11 RXEN=RX1EN RXIQSEL=RX1IQSEL SCLK=SCLK1 SEN=SEN1 TX=TX TXCLK=TX1CLK TXD0=TX1D0 TXD1=TX1D1 TXD2=TX1D2 TXD3=TX1D3 TXD4=TX1D4 TXD5=TX1D5 TXD6=TX1D6 TXD7=TX1D7 TXD8=TX1D8 TXD9=TX1D9 TXD10=TX1D10 TXD11=TX1D11 TXEN=TX1EN TXIQSEL=TX1IQSEL
LMS-b: designators end in -2; ports LMS_nRST=LMS2_nRST MISO=MISO2 MOSI=MOSI2 PLLCLK=PLL2CLK RX=RX RX_CLK/2=RX2_CLK/2 RXCLK=RX2CLK RXD0=RX2D0 RXD1=RX2D1 RXD2=RX2D2 RXD3=RX2D3 RXD4=RX2D4 RXD5=RX2D5 RXD6=RX2D6 RXD7=RX2D7 RXD8=RX2D8 RXD9=RX2D9 RXD10=RX2D10 RXD11=RX2D11 RXEN=RX2EN RXIQSEL=RX2IQSEL SCLK=SCLK2 SEN=SEN2 TX=TX TXCLK=TX2CLK TXD0=TX2D0 TXD1=TX2D1 TXD2=TX2D2 TXD3=TX2D3 TXD4=TX2D4 TXD5=TX2D5 TXD6=TX2D6 TXD7=TX2D7 TXD8=TX2D8 TXD9=TX2D9 TXD10=TX2D10 TXD11=TX2D11 TXEN=TX2EN TXIQSEL=TX2IQSEL

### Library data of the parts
C44 C46-C50 C55-C63 C69-C72 C78-C80 C85-C94 = C0402: as C25-C27 on sheet EEpromConfig
C45 C82-C84 C95-C99 C102-C107 C110-C112 = C0603: as C19 on sheet Clocking
C51-C54 = CD7343: as C6 on sheet Clocking
C64-C67 = CA3216: Конденсатор; Manufacturer: SPRAGUE; Name: Case A; U/P/TKE: 16V
C68 C73-C77 C81 C100 C101 C108 C109 = C0603: as C316 on sheet EEpromConfig
L6-L29 = TI160808: Дроссель ЭМС; Manufacturer: MURATA
L30-L33 = TF160808: Индуктивность; Manufacturer: SMD
R95-R127 R154-R159 = R0603: as R14-R38 on sheet EEpromConfig
T1 T2 = TC1-1-13: Трансформатор; Manufacturer: Mini-Cirquits; PDF: d:\Proj\Components\Mini-Circuits\TC1-1-13MG2+.pdf; Misc: RF Transformer
T3 = TC4-25: Трансформатор; Manufacturer: Mini-Cirquits; PDF: d:\Proj\Components\Mini-Circuits\TC4-25+.pdf; Misc: RF Transformer
U12 = LMS6002D: Микросхема; Manufacturer: Lime Microsystems; Misc: Multi-band Multi-standard  Transceiver with Digital Interface
U13 U14 = AD8130: Микросхема; Manufacturer: TI; Misc: 270MHz Diff Amp; Swap: No
U29 = LD1117FIX: Микросхема; Manufacturer: STMicro; Swap: No
U30-U32 = LD1117ADJ: as U28 on sheet Clocking
X12-X17 = KP: Контактная площадка; Manufacturer: Конструктив
Z1 = NFM3DP: Фильтр; Manufacturer: Murata; Misc: Фильтр электромагнитных помех; Value: 0.022uF; PDF: D:\DataSheets\MuRata\EMI_FILTERS.pdf

## Sheet LNA_DIV.SchDoc
size A3; Revision: 1; SheetNumber: 3
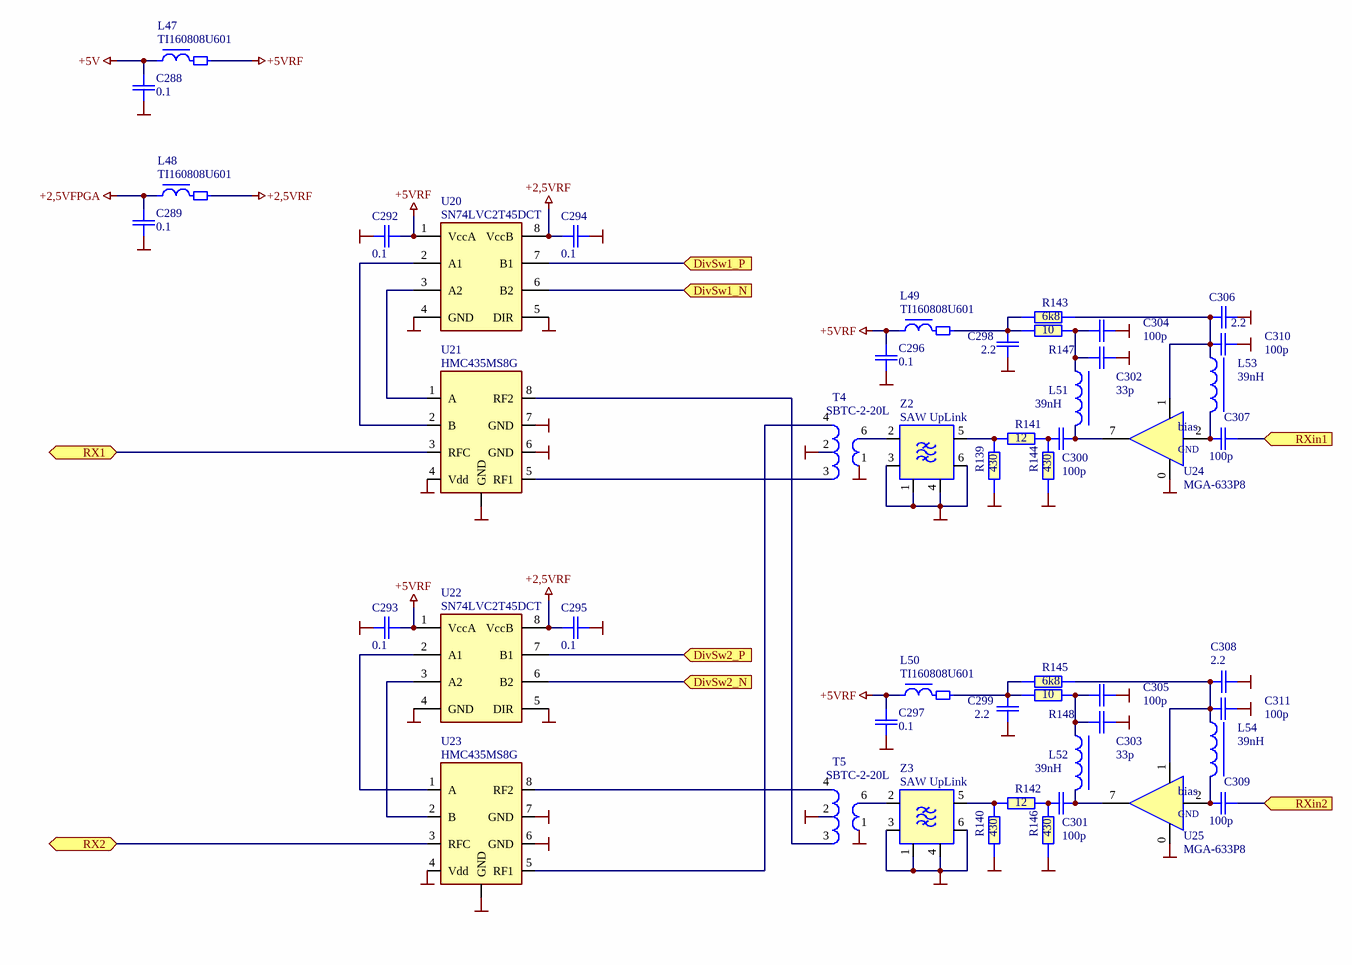
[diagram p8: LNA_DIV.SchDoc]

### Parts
C288  0.1  [C0402-Phillips]
C289  0.1  [C0402-Phillips]
C292  0.1  [C0402-Phillips]
C293  0.1  [C0402-Phillips]
C294  0.1  [C0402-Phillips]
C295  0.1  [C0402-Phillips]
C296  0.1  [C0402-Phillips]
C297  0.1  [C0402-Phillips]
C298  2.2  [C0402-Phillips]
C299  2.2  [C0402-Phillips]
C300  100p  [C0603-PHILLIPS]
C301  100p  [C0603-PHILLIPS]
C302  33p  [C0603-PHILLIPS]
C303  33p  [C0603-PHILLIPS]
C304  100p  [C0603-PHILLIPS]
C305  100p  [C0603-PHILLIPS]
C306  2.2  [C0402-Phillips]
C307  100p  [C0603-PHILLIPS]
C308  2.2  [C0402-Phillips]
C309  100p  [C0603-PHILLIPS]
C310  100p  [C0603-PHILLIPS]
C311  100p  [C0603-PHILLIPS]
L47  TI160808U601  [Ti160808-Phillips]
L48  TI160808U601  [Ti160808-Phillips]
L49  TI160808U601  [Ti160808-Phillips]
L50  TI160808U601  [Ti160808-Phillips]
L51  39nH  [TF160808-Phillips]
L52  39nH  [TF160808-Phillips]
L53  39nH  [TF160808-Phillips]
L54  39nH  [TF160808-Phillips]
R139  430  [R0603-PHILLIPS]
R140  430  [R0603-PHILLIPS]
R141  12  [R0603-PHILLIPS]
R142  12  [R0603-PHILLIPS]
R143  6k8  [R0603-PHILLIPS]
R144  430  [R0603-PHILLIPS]
R145  6k8  [R0603-PHILLIPS]
R146  430  [R0603-PHILLIPS]
R147  10  [R0603-PHILLIPS]
R148  10  [R0603-PHILLIPS]
T4  SBTC-2-20L  [AT1030]
T5  SBTC-2-20L  [AT1030]
U20  SN74LVC2T45DCT  [SO-8-MICRO]
U21  HMC435MS8G  [MS8G]
U22  SN74LVC2T45DCT  [SO-8-MICRO]
U23  HMC435MS8G  [MS8G]
U24  MGA-633P8  [SLP2x2]
U25  MGA-633P8  [SLP2x2]
Z2  SAW UpLink  [DCC6C_L]
Z3  SAW UpLink  [DCC6C_L]

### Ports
DivSw1_N (in), DivSw1_P (in), DivSw2_N (in), DivSw2_P (in), RX1, RX2, RXin1 (in), RXin2 (in)

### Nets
+2,5VFPGA: C289.1 L48.1
+2,5VRF: C294.2 C295.2 L48.2 U20.8(VccB) U22.8(VccB)
+5V: C288.1 L47.1
+5VRF: C292.1 C293.1 C296.1 C297.1 L47.2 L49.1 L50.1 U20.1(VccA) U22.1(VccA)
GND: C288.2 C289.2 C292.2 C293.2 C294.1 C295.1 C296.2 C297.2 C298.1 C299.1 C302.2 C303.2 C304.2 C305.2 C306.1 C308.1 C310.2 C311.2 R139.1 R140.1 R144.1 R146.1 T4.1 T4.2 T5.1 T5.2 U20.4(GND) U20.5(DIR) U21.0(GND) U21.4(Vdd) U21.6(GND) U21.7(GND) U22.4(GND) U22.5(DIR) U23.0(GND) U23.4(Vdd) U23.6(GND) U23.7(GND) U24.0(GND) U25.0(GND) Z2.1(GND) Z2.3(GND) Z2.4(GND) Z2.6(GND) Z3.1(GND) Z3.3(GND) Z3.4(GND) Z3.6(GND)
DivSw1_N: U20.6(B2) ; port DivSw1_N
DivSw1_P: U20.7(B1) ; port DivSw1_P
DivSw2_N: U22.6(B2) ; port DivSw2_N
DivSw2_P: U22.7(B1) ; port DivSw2_P
RX: U21.3(RFC) ; port RX1
RX: U23.3(RFC) ; port RX2  [a separate net that carries the same name]
RXin1: C307.2 ; port RXin1
RXin2: C309.2 ; port RXin2
NetC298_2: C298.2 L49.2 R143.1 R147.1
NetC299_2: C299.2 L50.2 R145.1 R148.1
NetC300_1: C300.1 R141.2 R144.2
NetC300_2: C300.2 L51.2 U24.7(RFout/VDD)
NetC301_1: C301.1 R142.2 R146.2
NetC301_2: C301.2 L52.2 U25.7(RFout/VDD)
NetC302_1: C302.1 C304.1 L51.1 R147.2
NetC303_1: C303.1 C305.1 L52.1 R148.2
NetC306_2: C306.2 C310.1 L53.1 R143.2 U24.1(BIAS)
NetC307_1: C307.1 L53.2 U24.2(A)
NetC308_2: C308.2 C311.1 L54.1 R145.2 U25.1(BIAS)
NetC309_1: C309.1 L54.2 U25.2(A)
NetR139_2: R139.2 R141.1 Z2.5(Out)
NetR140_2: R140.2 R142.1 Z3.5(Out)
NetT4_3: T4.3 U21.5(RF1)
NetT4_4: T4.4 U23.5(RF1)
NetT4_6: T4.6 Z2.2(IN)
NetT5_3: T5.3 U21.8(RF2)
NetT5_4: T5.4 U23.8(RF2)
NetT5_6: T5.6 Z3.2(IN)
NetU20_2: U20.2(A1) U21.2(B)
NetU20_3: U20.3(A2) U21.1(A)
NetU22_2: U22.2(A1) U23.1(A)
NetU22_3: U22.3(A2) U23.2(B)

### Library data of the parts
C288 C289 C292-C299 C306 C308 = C0402: as C25-C27 on sheet EEpromConfig
C300-C305 C307 C309-C311 = C0603: as C19 on sheet Clocking
L47-L50 = TI160808: Дроссель ЭМС; Manufacturer: MURATA
L51-L54 = TF160808: Индуктивность; Manufacturer: SMD
R139-R148 = R0603: as R14-R38 on sheet EEpromConfig
T4 T5 = SBTC-2-10L: Трансформатор; Manufacturer: Mini-Cirquits
U20 U22 = 74LVC2T45DCT: Микросхема; Manufacturer: TI; Swap: No
U21 U23 = HMC435MS8G: Микросхема; Manufacturer: Hittite; Swap: No; Misc: High IP3 Mixer with  LO Amp
U24 U25 = MGA-633P8: Микросхема; Manufacturer: Avago; Swap: No; Misc: Ultra Low Noise, High Linearity Active Bias Low Noise Amplifi er; PDF: d:\Proj\Components\Avago\MGA-633P8.pdf
Z2 Z3 = SAW 3x3 SMD: Фильтр ПАВ; Manufacturer: MuRata; Misc: Low-Loss Filter for Mobile Communication

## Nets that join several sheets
+2,5VETH: PwrAndBias (22 pins), GBEthernet (12 pins)
+2,5VFPGA: PwrAndBias (65 pins), Clocking (C24.1 L3.2), LNA_DIV (C289.1 L48.1)
+2,5VRAM: PwrAndBias (30 pins), FPGA_RAM (U11.97)
+3,3VFPGA: PwrAndBias (53 pins), GBEthernet (C42.1 L5.2), EEpromConfig (27 pins)
+5V: PwrAndBias (5 pins), Clocking (C4.1 L1.1), LMS-a (R126-1.2), LNA_DIV (C288.1 L47.1), LMS-b (R126-2.2)
+6.5V: PwrAndBias (C125.1 C127.1 L34.2 U18.3), LMS-a (C44-1.1 Z1-1.1), LMS-b (C44-2.1 Z1-2.1)
+12V: PwrAndBias (20 pins), EEpromConfig (X26.1)
-5V: PwrAndBias (C160.1 C169.1 L44.2), LMS-a (R127-1.2), LMS-b (R127-2.2)
GND: Total (6 pins), PwrAndBias (265 pins), FPGA_RAM (6 pins), GBEthernet (23 pins), EEpromConfig (47 pins), Clocking (52 pins), LMS-a (90 pins), LNA_DIV (48 pins), LMS-b (90 pins)
CLK_FPGA_N: FPGA_RAM (U8.L19), Clocking (U5.9)
CLK_FPGA_P: FPGA_RAM (U8.M20), Clocking (U5.10)
CLK_TO_MAC: FPGA_RAM (U8.G20), GBEthernet (U9.57)
CLKIO: Total (X7.1), Clocking (SW3.2)
DAC_CLK: EEpromConfig (U8.AB19), Clocking (U1.5)
DAC_DIN: EEpromConfig (U8.AA18), Clocking (U1.4)
DAC_NSY: EEpromConfig (U8.Y19), Clocking (U1.6)
DivSw1_N: FPGA_RAM (U8.K1), LNA_DIV (U20.6)
DivSw1_P: FPGA_RAM (U8.K2), LNA_DIV (U20.7)
DivSw2_N: FPGA_RAM (U8.M1), LNA_DIV (U22.6)
DivSw2_P: FPGA_RAM (U8.M2), LNA_DIV (U22.7)
ETH_LEDG: GBEthernet (R44.2), EEpromConfig (U8.Y15)
ETH_LEDO: GBEthernet (R42.2), EEpromConfig (U8.W12)
FAN_ON: PwrAndBias (U35.4), EEpromConfig (U8.AB14)
GMII_COL: FPGA_RAM (U8.N22), GBEthernet (RA2.11)
GMII_CRS: FPGA_RAM (U8.P20), GBEthernet (RA2.12)
GMII_GTX_CLK: FPGA_RAM (U8.H21), GBEthernet (RA2.14)
GMII_RX_CLK: FPGA_RAM (U8.H22), GBEthernet (RA2.10)
GMII_RX_DV: FPGA_RAM (U8.L22), GBEthernet (RA3.16)
GMII_RX_ER: FPGA_RAM (U8.M22), GBEthernet (RA2.9)
GMII_RXD0: FPGA_RAM (U8.L20), GBEthernet (RA3.15)
GMII_RXD1: FPGA_RAM (U8.K22), GBEthernet (RA3.14)
GMII_RXD2: FPGA_RAM (U8.K21), GBEthernet (RA3.13)
GMII_RXD3: FPGA_RAM (U8.F18), GBEthernet (RA3.12)
GMII_RXD4: FPGA_RAM (U8.J20), GBEthernet (RA3.11)
GMII_RXD5: FPGA_RAM (U8.F19), GBEthernet (RA3.10)
GMII_RXD6: FPGA_RAM (U8.F20), GBEthernet (RA3.9)
GMII_RXD7: FPGA_RAM (U8.G22), GBEthernet (R90.1)
GMII_TX_CLK: FPGA_RAM (U8.J22), GBEthernet (RA2.13)
GMII_TX_EN: FPGA_RAM (U8.T19), GBEthernet (RA2.16)
GMII_TX_ER: FPGA_RAM (U8.R22), GBEthernet (RA2.15)
GMII_TXD0: FPGA_RAM (U8.T22), GBEthernet (RA1.9)
GMII_TXD1: FPGA_RAM (U8.T21), GBEthernet (RA1.10)
GMII_TXD2: FPGA_RAM (U8.U22), GBEthernet (RA1.11)
GMII_TXD3: FPGA_RAM (U8.U20), GBEthernet (RA1.12)
GMII_TXD4: FPGA_RAM (U8.V22), GBEthernet (RA1.13)
GMII_TXD5: FPGA_RAM (U8.V21), GBEthernet (RA1.14)
GMII_TXD6: FPGA_RAM (U8.W22), GBEthernet (RA1.15)
GMII_TXD7: FPGA_RAM (U8.W20), GBEthernet (RA1.16)
GPS_ANT: Total (X6.1), Clocking (U4.1)
LMS1_nRST: FPGA_RAM (U8.L3), LMS-a (R95-1.1 U12-1.75)
LMS2_nRST: FPGA_RAM (U8.Y1), LMS-b (R95-2.1 U12-2.75)
MDC: FPGA_RAM (U8.F22), GBEthernet (U9.55)
MDIO: FPGA_RAM (U8.F21), GBEthernet (R92.2 U9.54)
MISO1: FPGA_RAM (U8.F2 X21.1), LMS-a (U12-1.68)
MISO2: FPGA_RAM (U8.N6 X25.1), LMS-b (U12-2.68)
MOSI1: FPGA_RAM (U8.E3 X20.1), LMS-a (U12-1.69)
MOSI2: FPGA_RAM (U8.M7 X24.1), LMS-b (U12-2.69)
OVERHEAT: PwrAndBias (R173.2 U35.6), EEpromConfig (U8.AB13)
PHY_INTN: FPGA_RAM (U8.E22), GBEthernet (R91.2 U9.53)
PHY_RESETn: FPGA_RAM (U8.R20), GBEthernet (U9.24)
PLL0CLK: EEpromConfig (X26.9), Clocking (R167.2)
PLL1CLK: Clocking (R160.2 R161.1), LMS-a (L6-1.1)
PLL2CLK: Clocking (R161.2 U5.21), LMS-b (L6-2.1)
PPS_IN: EEpromConfig (U8.AB18), Clocking (U26.6 U27.3)
RX: LMS-a (C111-1.1 C112-1.2), LNA_DIV (U21.3)
RX: LNA_DIV (U23.3), LMS-b (C111-2.1 C112-2.2)
RX1_CLK/2: FPGA_RAM (U8.G3), LMS-a (U12-1.40)
RX1CLK: Clocking (U5.18), LMS-a (R158-1.2 R159-1.1 U12-1.17)
RX1D0: FPGA_RAM (U8.J1), LMS-a (U12-1.15)
RX1D1: FPGA_RAM (U8.L6), LMS-a (U12-1.14)
RX1D2: FPGA_RAM (U8.H3), LMS-a (U12-1.13)
RX1D3: FPGA_RAM (U8.K6), LMS-a (U12-1.10)
RX1D4: FPGA_RAM (U8.K5), LMS-a (U12-1.11)
RX1D5: FPGA_RAM (U8.H2), LMS-a (U12-1.8)
RX1D6: FPGA_RAM (U8.J3), LMS-a (U12-1.9)
RX1D7: FPGA_RAM (U8.K4), LMS-a (U12-1.6)
RX1D8: FPGA_RAM (U8.J6), LMS-a (U12-1.5)
RX1D9: FPGA_RAM (U8.M8), LMS-a (U12-1.4)
RX1D10: FPGA_RAM (U8.J7), LMS-a (U12-1.3)
RX1D11: FPGA_RAM (U8.N7), LMS-a (U12-1.2)
RX1EN: FPGA_RAM (U8.L1), LMS-a (U12-1.76)
RX1IQSEL: FPGA_RAM (U8.J4), LMS-a (U12-1.16)
RX2_CLK/2: FPGA_RAM (U8.N1), LMS-b (U12-2.40)
RX2CLK: Clocking (U5.17), LMS-b (R158-2.2 R159-2.1 U12-2.17)
RX2D0: FPGA_RAM (U8.T2), LMS-b (U12-2.15)
RX2D1: FPGA_RAM (U8.T3), LMS-b (U12-2.14)
RX2D2: FPGA_RAM (U8.U1), LMS-b (U12-2.13)
RX2D3: FPGA_RAM (U8.T4), LMS-b (U12-2.10)
RX2D4: FPGA_RAM (U8.V3), LMS-b (U12-2.11)
RX2D5: FPGA_RAM (U8.T1), LMS-b (U12-2.8)
RX2D6: FPGA_RAM (U8.U3), LMS-b (U12-2.9)
RX2D7: FPGA_RAM (U8.U4), LMS-b (U12-2.6)
RX2D8: FPGA_RAM (U8.V2), LMS-b (U12-2.5)
RX2D9: FPGA_RAM (U8.V1), LMS-b (U12-2.4)
RX2D10: FPGA_RAM (U8.W1), LMS-b (U12-2.3)
RX2D11: FPGA_RAM (U8.W3), LMS-b (U12-2.2)
RX2EN: FPGA_RAM (U8.Y2), LMS-b (U12-2.76)
RX2IQSEL: FPGA_RAM (U8.P8), LMS-b (U12-2.16)
RXD2: EEpromConfig (U8.Y17), Clocking (R65.1)
RXin1: Total (X9.1), LNA_DIV (C307.2)
RXin2: Total (X10.1), LNA_DIV (C309.2)
SCLK1: FPGA_RAM (U8.F1 X19.1), LMS-a (U12-1.70)
SCLK2: FPGA_RAM (U8.H5 X23.1), LMS-b (U12-2.70)
SEN1: FPGA_RAM (U8.E1 X18.1), LMS-a (U12-1.67)
SEN2: FPGA_RAM (U8.M4 X22.1), LMS-b (U12-2.67)
TX: Total (X8.1), LMS-a (C110-1.2)
TX: Total (X11.1), LMS-b (C110-2.2)
TX1CLK: FPGA_RAM (U8.K3), Clocking (U5.14), LMS-a (R154-1.2 R155-1.2 U12-1.19)
TX1D0: FPGA_RAM (U8.H4), LMS-a (U12-1.21)
TX1D1: FPGA_RAM (U8.H8), LMS-a (U12-1.22)
TX1D2: FPGA_RAM (U8.G4), LMS-a (U12-1.23)
TX1D3: FPGA_RAM (U8.G7), LMS-a (U12-1.24)
TX1D4: FPGA_RAM (U8.F5), LMS-a (U12-1.25)
TX1D5: FPGA_RAM (U8.F7), LMS-a (U12-1.26)
TX1D6: FPGA_RAM (U8.G6), LMS-a (U12-1.27)
TX1D7: FPGA_RAM (U8.E5), LMS-a (U12-1.28)
TX1D8: FPGA_RAM (U8.F3), LMS-a (U12-1.29)
TX1D9: FPGA_RAM (U8.E4), LMS-a (U12-1.30)
TX1D10: FPGA_RAM (U8.H1), LMS-a (U12-1.31)
TX1D11: FPGA_RAM (U8.E6), LMS-a (U12-1.32)
TX1EN: FPGA_RAM (U8.G1), LMS-a (U12-1.66)
TX1IQSEL: FPGA_RAM (U8.H6), LMS-a (U12-1.20)
TX2CLK: FPGA_RAM (U8.M3), Clocking (U5.13), LMS-b (R154-2.2 R155-2.2 U12-2.19)
TX2D0: FPGA_RAM (U8.R3), LMS-b (U12-2.21)
TX2D1: FPGA_RAM (U8.L4), LMS-b (U12-2.22)
TX2D2: FPGA_RAM (U8.R1), LMS-b (U12-2.23)
TX2D3: FPGA_RAM (U8.K7), LMS-b (U12-2.24)
TX2D4: FPGA_RAM (U8.P2), LMS-b (U12-2.25)
TX2D5: FPGA_RAM (U8.K8), LMS-b (U12-2.26)
TX2D6: FPGA_RAM (U8.P1), LMS-b (U12-2.27)
TX2D7: FPGA_RAM (U8.P4), LMS-b (U12-2.28)
TX2D8: FPGA_RAM (U8.P5), LMS-b (U12-2.29)
TX2D9: FPGA_RAM (U8.P6), LMS-b (U12-2.30)
TX2D10: FPGA_RAM (U8.P3), LMS-b (U12-2.31)
TX2D11: FPGA_RAM (U8.N3), LMS-b (U12-2.32)
TX2EN: FPGA_RAM (U8.N4), LMS-b (U12-2.66)
TX2IQSEL: FPGA_RAM (U8.M5), LMS-b (U12-2.20)
TXD2: EEpromConfig (U8.AB17), Clocking (U4.6)

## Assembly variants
UmTRX v0.1a: not fitted C111-1 C111-2 R2 R6 R12 R125-1 R125-2 R154-1 R154-2 R155-1 R155-2 R156-1 R156-2 R157-1 R157-2 R158-1 R158-2 R159-1 R159-2 R161 U2
Variant of SDRv1: all parts fitted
